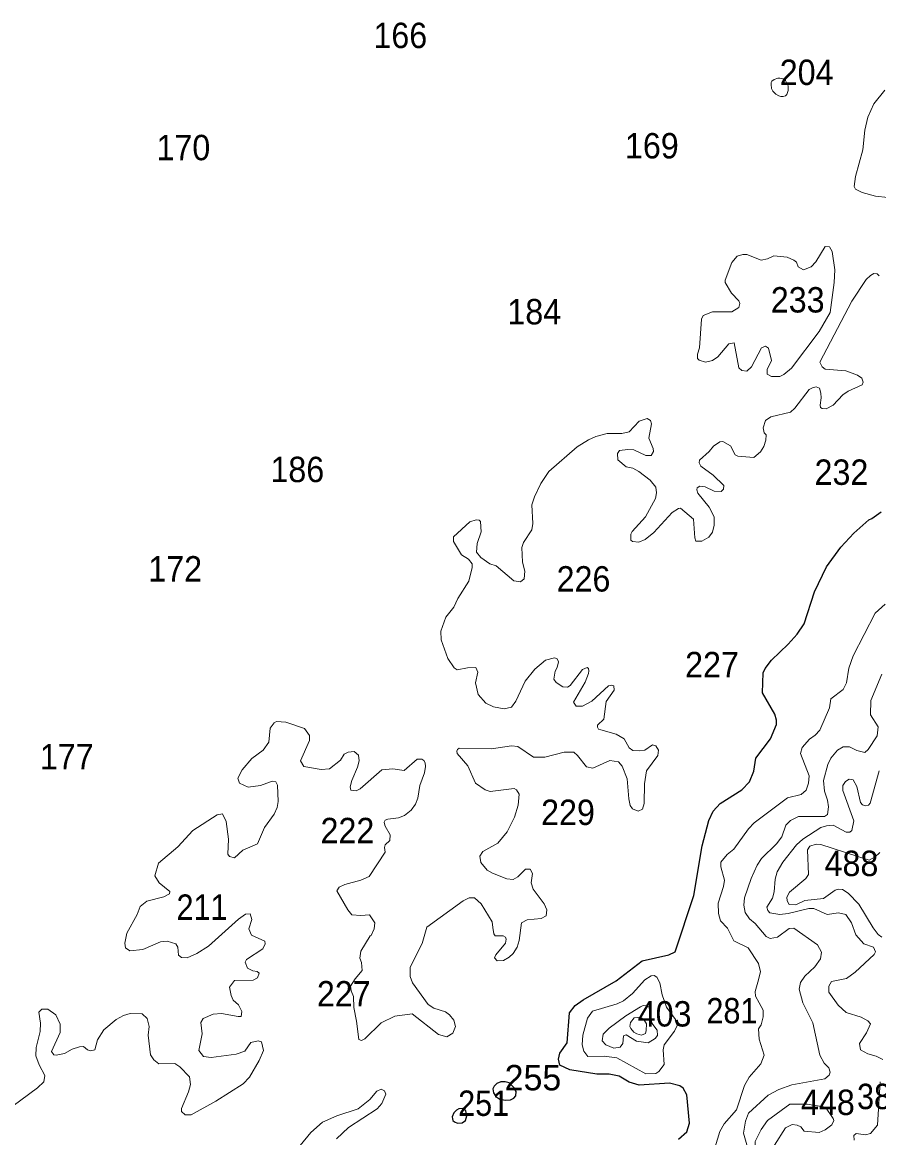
# Model space of a CAD drawing. Extents: x 499.9 to 555.3, y 9281.5 to 9336.8.
# Drawn here: x 530.94 to 536.34, y 9298.96 to 9305.99 of the extents above; entities that cross this region are included whole.
import ezdxf

# ---------------------------------------------------------------- set-up
doc = ezdxf.new("R2010")
doc.units = 0
doc.header["$LTSCALE"] = 0.064
doc.layers.add('1', color=7, linetype='Continuous', lineweight=25)
doc.layers.add('2', color=7, linetype='Continuous', lineweight=13)
doc.layers.add('21', color=7, linetype='Continuous')

msp = doc.modelspace()

# ---------------------------------------------------------------- linework, layer by layer
at = {"layer": '1'}
msp.add_lwpolyline([(535.0738, 9298.9508), (535.1263, 9298.9978), (535.1424, 9299.0519), (535.1247, 9299.2307), (535.1031, 9299.2737), (535.0811, 9299.2869), (535.016, 9299.3047), (534.8252, 9299.2909), (534.7623, 9299.3114), (534.6985, 9299.3493), (534.6349, 9299.362), (534.5573, 9299.3606), (534.387, 9299.3881), (534.3255, 9299.4173), (534.3158, 9299.4551), (534.3253, 9299.494), (534.3712, 9299.5597), (534.3857, 9299.7479), (534.4217, 9299.7933), (534.4724, 9299.8301), (534.6801, 9299.9499), (534.8444, 9300.0746), (535.0113, 9300.1132), (535.0516, 9300.1311), (535.1694, 9300.4866), (535.2214, 9300.7991), (535.2639, 9300.9592), (535.2919, 9301.0181), (535.3352, 9301.0666), (535.4726, 9301.1533), (535.5211, 9301.2038), (535.5483, 9301.2705), (535.5599, 9301.353), (535.6529, 9301.4751), (535.6913, 9301.5656), (535.6916, 9301.5919), (535.6804, 9301.6301), (535.6028, 9301.7639), (535.6064, 9301.8894), (535.619, 9301.9173), (535.6594, 9301.97), (535.7649, 9302.0712), (535.8205, 9302.1347), (535.8646, 9302.1993), (535.9308, 9302.4012), (536.0057, 9302.5587), (536.0954, 9302.6814), (536.1775, 9302.7699), (536.2727, 9302.8554), (536.2923, 9302.8632), (536.3497, 9302.9054)], dxfattribs=at)
for points in [[(533.9068, 9299.2428), (533.9217, 9299.2212), (533.9466, 9299.2046), (533.9832, 9299.198), (534.0131, 9299.1996), (534.0347, 9299.2096), (534.048, 9299.2246), (534.0497, 9299.2528), (534.0347, 9299.2777), (534.0048, 9299.3076), (533.9799, 9299.3126), (533.9533, 9299.3126), (533.9284, 9299.3027), (533.9101, 9299.286), (533.9018, 9299.2678)], [(533.6559, 9299.1182), (533.6459, 9299.0916), (533.6475, 9299.08), (533.6509, 9299.0684), (533.6608, 9299.0601), (533.6791, 9299.0534), (533.709, 9299.0551), (533.7306, 9299.07), (533.7389, 9299.0983), (533.7323, 9299.1298), (533.7123, 9299.1448), (533.6874, 9299.1431), (533.6725, 9299.1348)]]:
    msp.add_lwpolyline(points, close=True, dxfattribs=at)
at = {"layer": '2'}
for points in [[(535.6873, 9305.536), (535.7047, 9305.5257), (535.7182, 9305.5212), (535.7337, 9305.5212), (535.7485, 9305.5263), (535.7556, 9305.5347), (535.764, 9305.5592), (535.764, 9305.5882), (535.7485, 9305.623), (535.7337, 9305.6339), (535.7124, 9305.6378), (535.6989, 9305.6365), (535.677, 9305.6294), (535.6615, 9305.6191), (535.657, 9305.6101), (535.6564, 9305.5985), (535.659, 9305.5727), (535.668, 9305.5566)], [(535.9596, 9304.042), (536.0294, 9304.161), (536.055, 9304.3501), (536.0578, 9304.4289), (536.042, 9304.5443), (536.0255, 9304.5742), (535.997, 9304.577), (535.9391, 9304.4797), (535.9096, 9304.449), (535.8612, 9304.4302), (535.8273, 9304.449), (535.816, 9304.4782), (535.8004, 9304.4913), (535.7585, 9304.5091), (535.6746, 9304.5187), (535.6336, 9304.4996), (535.5938, 9304.4905), (535.5047, 9304.5264), (535.4794, 9304.5265), (535.4429, 9304.5149), (535.4082, 9304.4751), (535.3675, 9304.3652), (535.3671, 9304.3499), (535.4077, 9304.2822), (535.4543, 9304.2339), (535.459, 9304.2172), (535.4527, 9304.1933), (535.4091, 9304.1656), (535.2876, 9304.1643), (535.2294, 9304.1417), (535.2175, 9304.1181), (535.2061, 9303.9381), (535.1922, 9303.8973), (535.193, 9303.8701), (535.204, 9303.8598), (535.2436, 9303.8488), (535.2867, 9303.8581), (535.3213, 9303.8812), (535.3896, 9303.963), (535.4234, 9303.9692), (535.4526, 9303.8118), (535.4713, 9303.7947), (535.5044, 9303.7918), (535.5325, 9303.8186), (535.596, 9303.9386), (535.6206, 9303.9484), (535.6408, 9303.937), (535.6596, 9303.8584), (535.6315, 9303.8026), (535.6315, 9303.7731), (535.659, 9303.7581), (535.7126, 9303.7579), (535.7378, 9303.7708), (535.7844, 9303.8111)], [(534.5008, 9299.4717), (534.4758, 9299.5055), (534.4658, 9299.5457), (534.4695, 9299.6068), (534.4997, 9299.7142), (534.53, 9299.7578), (534.6873, 9299.8041), (534.7256, 9299.8229), (534.7833, 9299.8687), (534.8609, 9299.9552), (534.9006, 9299.9799), (534.9197, 9299.9825), (534.9367, 9299.972), (534.9559, 9299.9374), (534.9708, 9299.8603), (534.998, 9299.7833), (535.0545, 9299.7049), (535.0642, 9299.6669), (535.0475, 9299.6312), (534.9823, 9299.5456), (534.9772, 9299.5141), (534.9822, 9299.4218), (534.9488, 9299.3788), (534.9298, 9299.3664), (534.8673, 9299.3639), (534.6842, 9299.4639), (534.6048, 9299.4751)], [(534.8088, 9299.5691), (534.7428, 9299.6096), (534.7265, 9299.6031), (534.722, 9299.5543), (534.7051, 9299.5308), (534.6643, 9299.5254), (534.6155, 9299.5462), (534.5926, 9299.5703), (534.5986, 9299.6133), (534.6365, 9299.651), (534.7409, 9299.7297), (534.8329, 9299.7855), (534.8505, 9299.793), (534.8713, 9299.7916), (534.8851, 9299.7863), (534.8935, 9299.7538), (534.904, 9299.6826), (534.9376, 9299.6386), (534.9403, 9299.6048), (534.9254, 9299.5861), (534.8822, 9299.5586)], [(534.7708, 9299.6865), (534.7659, 9299.6616), (534.7725, 9299.65), (534.7908, 9299.6267), (534.8107, 9299.6151), (534.8396, 9299.6075), (534.8639, 9299.6167), (534.8689, 9299.6367), (534.8705, 9299.6782), (534.8539, 9299.7064), (534.8323, 9299.7197), (534.7941, 9299.7164)], [(535.8644, 9299.0025), (535.8436, 9299.0294), (535.8203, 9299.0409), (535.7888, 9299.0448), (535.7476, 9299.0225), (535.6781, 9298.9146), (535.6147, 9298.8555), (535.584, 9298.8541), (535.5631, 9298.8647), (535.5543, 9298.8836), (535.5559, 9298.9361), (535.594, 9299.0122), (535.6348, 9299.0691), (535.7746, 9299.1726), (535.885, 9299.1714), (535.9996, 9299.1534), (536.049, 9299.0818), (536.0525, 9299.0686), (536.0402, 9299.0411), (535.9979, 9299.0109), (535.9591, 9298.9928)]]:
    msp.add_lwpolyline(points, close=True, dxfattribs=at)
for points in [[(536.3918, 9304.8849), (536.3149, 9304.8931), (536.2313, 9304.916), (536.1889, 9304.9372), (536.1807, 9304.9543), (536.189, 9305.0172), (536.2342, 9305.185), (536.2471, 9305.3098), (536.2676, 9305.3919), (536.3045, 9305.4753), (536.3729, 9305.5611)], [(535.1754, 9302.7402), (535.1819, 9302.7201), (535.2194, 9302.7197), (535.265, 9302.746), (535.2869, 9302.7771), (535.2969, 9302.8214), (535.2969, 9302.8734), (535.2671, 9302.9343), (535.1952, 9303.022), (535.1881, 9303.0434), (535.1898, 9303.056), (535.2078, 9303.0662), (535.2406, 9303.0625), (535.2976, 9303.034), (535.3419, 9303.0338), (535.3561, 9303.047), (535.3584, 9303.0714), (535.2921, 9303.136), (535.2131, 9303.1929), (535.2036, 9303.2132), (535.2058, 9303.2307), (535.2661, 9303.2848), (535.2938, 9303.3186), (535.3345, 9303.3468), (535.3531, 9303.3486), (535.4018, 9303.3201), (535.4307, 9303.263), (535.4474, 9303.2552), (535.5473, 9303.2477), (535.5894, 9303.2837), (535.6104, 9303.3172), (535.6242, 9303.3568), (535.6247, 9303.391), (535.6123, 9303.4034), (535.6061, 9303.4333), (535.6223, 9303.48), (535.656, 9303.5031), (535.7789, 9303.533), (535.8059, 9303.557), (535.8972, 9303.675), (535.9169, 9303.6871), (535.94, 9303.6926), (535.962, 9303.6831), (535.9696, 9303.6518), (535.9718, 9303.6227), (535.9652, 9303.5769), (535.9674, 9303.5626), (535.9792, 9303.5552), (536.0029, 9303.553), (536.0487, 9303.5771), (536.1083, 9303.6412), (536.1422, 9303.6647), (536.2302, 9303.7053), (536.2372, 9303.7221), (536.2297, 9303.7461), (536.2025, 9303.7652), (536.1278, 9303.793), (535.9983, 9303.8032), (535.9779, 9303.8177), (535.9643, 9303.8481), (536.1648, 9304.2319), (536.2557, 9304.3692), (536.2828, 9304.3942), (536.3038, 9304.4069), (536.3263, 9304.4038), (536.3378, 9304.3929)], [(534.3737, 9301.8007), (534.3446, 9301.801), (534.3017, 9301.8283), (534.288, 9301.8504), (534.2945, 9301.9016), (534.3072, 9301.9237), (534.3163, 9301.9592), (534.3072, 9301.9779), (534.2916, 9301.9847), (534.2344, 9301.9708), (534.1663, 9301.9125), (534.1066, 9301.837), (534.0484, 9301.7114), (534.0197, 9301.6746), (533.9742, 9301.6637), (533.9062, 9301.6754), (533.8589, 9301.6998), (533.81, 9301.7527), (533.7931, 9301.8267), (533.8068, 9301.8936), (533.7943, 9301.9236), (533.7437, 9301.9213), (533.6785, 9301.9089), (533.6594, 9301.9217), (533.618, 9301.9801), (533.5768, 9302.0973), (533.5751, 9302.1521), (533.6066, 9302.2406), (533.6571, 9302.3043), (533.6825, 9302.3592), (533.7521, 9302.4689), (533.7722, 9302.5532), (533.7721, 9302.5779), (533.7483, 9302.6073), (533.704, 9302.6346), (533.6549, 9302.7181), (533.6551, 9302.7462), (533.7565, 9302.8411), (533.7977, 9302.8539), (533.8153, 9302.8528), (533.8251, 9302.8437), (533.8294, 9302.7784), (533.8041, 9302.706), (533.7994, 9302.6498), (533.826, 9302.616), (533.8831, 9302.5776), (533.9224, 9302.5638), (534.0345, 9302.4695), (534.0768, 9302.4632), (534.0997, 9302.482), (534.1031, 9302.5304), (534.0901, 9302.5883), (534.0844, 9302.6806), (534.0947, 9302.7108), (534.1476, 9302.7921), (534.1555, 9302.8316), (534.1482, 9302.9484), (534.1654, 9302.9989), (534.206, 9303.0833), (534.2555, 9303.1599), (534.4332, 9303.3138), (534.506, 9303.3593), (534.5522, 9303.3798), (534.623, 9303.3983), (534.7153, 9303.3985), (534.7616, 9303.4084), (534.826, 9303.4761), (534.8746, 9303.4935), (534.8956, 9303.4793), (534.902, 9303.4587), (534.8867, 9303.3692), (534.9134, 9303.3038), (534.9147, 9303.2854), (534.9005, 9303.2606), (534.8673, 9303.2602), (534.7916, 9303.2946), (534.7534, 9303.298), (534.7014, 9303.2919), (534.6892, 9303.2734), (534.6914, 9303.2321), (534.7432, 9303.1885), (534.7852, 9303.1799), (534.8227, 9303.1596), (534.8948, 9303.1048), (534.9309, 9303.06), (534.934, 9303.0243), (534.928, 9302.9879), (534.864, 9302.8732), (534.781, 9302.7817), (534.772, 9302.7633), (534.7722, 9302.7254), (534.7838, 9302.7172), (534.8219, 9302.7141), (534.8628, 9302.7295), (534.9177, 9302.7755)], [(534.9177, 9302.7755), (535.0338, 9302.9011), (535.0725, 9302.9254), (535.0863, 9302.927), (535.1665, 9302.8595), (535.1754, 9302.7402)], [(536.1111, 9301.7846), (536.1326, 9301.8267), (536.1469, 9301.9198), (536.1734, 9301.9971), (536.3133, 9302.2656), (536.3764, 9302.3227)], [(534.5081, 9301.9035), (534.5051, 9301.917), (534.4963, 9301.924), (534.4673, 9301.9112), (534.3901, 9301.8108), (534.3737, 9301.8007)], [(533.9683, 9300.2329), (533.9822, 9300.2251), (533.986, 9300.2109), (533.9813, 9300.1868), (533.922, 9300.1133), (533.9127, 9300.0937), (533.93, 9300.0755), (533.9688, 9300.0768), (534.0046, 9300.0975), (534.0309, 9300.1223), (534.0551, 9300.1621), (534.0682, 9300.2041), (534.0834, 9300.3142), (534.1187, 9300.3343), (534.2069, 9300.3418), (534.2381, 9300.3588), (534.2431, 9300.3974), (534.2253, 9300.4339), (534.1573, 9300.5264), (534.1447, 9300.5675), (534.1524, 9300.6267), (534.1369, 9300.6522), (534.1077, 9300.6523), (534.0592, 9300.6042), (534.0316, 9300.5885), (533.9905, 9300.5922), (533.9001, 9300.6275), (533.866, 9300.6469), (533.8266, 9300.6944), (533.8205, 9300.7356), (533.8397, 9300.7645), (533.9339, 9300.8165), (533.9927, 9300.8886), (534.0381, 9300.9799), (534.0619, 9301.0572), (534.0681, 9301.1264), (534.0525, 9301.152), (534.0364, 9301.1604), (533.8846, 9301.1433), (533.8534, 9301.1521), (533.7938, 9301.194), (533.744, 9301.3047), (533.6773, 9301.3817), (533.6746, 9301.3967), (533.6799, 9301.4073), (533.6902, 9301.4146), (533.894, 9301.4105), (534.0205, 9301.4295), (534.0601, 9301.4265), (534.1589, 9301.359), (534.2306, 9301.3597), (534.3531, 9301.3911), (534.4122, 9301.3899), (534.4369, 9301.3696), (534.4936, 9301.2972), (534.5322, 9301.2897), (534.6405, 9301.3368), (534.6941, 9301.3303), (534.7179, 9301.3015), (534.7489, 9301.2213), (534.759, 9301.0961), (534.7684, 9301.0548), (534.7836, 9301.033), (534.8189, 9301.0193), (534.8462, 9301.0305), (534.8559, 9301.066), (534.8592, 9301.1901), (534.8707, 9301.2735), (534.9428, 9301.3694), (534.9466, 9301.4024), (534.9307, 9301.4309), (534.9087, 9301.4371), (534.8601, 9301.4025), (534.8298, 9301.3979), (534.7847, 9301.4012), (534.7621, 9301.4175), (534.7298, 9301.4743), (534.6794, 9301.5043), (534.5837, 9301.5312), (534.5686, 9301.5363), (534.5621, 9301.5478), (534.5624, 9301.5606), (534.603, 9301.5976), (534.6173, 9301.7089), (534.6664, 9301.7814), (534.6662, 9301.8079), (534.6517, 9301.8128), (534.631, 9301.8077), (534.5255, 9301.7119), (534.4667, 9301.6807), (534.4272, 9301.6812), (534.4114, 9301.7063), (534.4837, 9301.8306), (534.5048, 9301.8863), (534.5081, 9301.9035)], [(535.5961, 9300.7212), (535.6911, 9300.8119), (535.7237, 9300.8574), (535.7493, 9300.9297), (535.7784, 9300.9607), (535.8286, 9300.9853), (535.9933, 9300.984), (536.0127, 9300.9969), (536.0195, 9301.0462), (536.0128, 9301.0888), (535.9944, 9301.1456), (535.9879, 9301.2115), (536.0135, 9301.3125), (536.0335, 9301.3525), (536.0745, 9301.4029), (536.1119, 9301.423), (536.1514, 9301.4247), (536.1964, 9301.4004), (536.2486, 9301.3886), (536.2682, 9301.408), (536.3249, 9301.4933), (536.3313, 9301.5499), (536.2827, 9301.6263), (536.2856, 9301.7168), (536.3551, 9301.8809)], [(535.8987, 9301.4725), (535.9336, 9301.4965), (535.9637, 9301.5283), (536.0252, 9301.6698), (536.0326, 9301.7255), (536.1111, 9301.7846)], [(532.3221, 9301.278), (532.3821, 9301.3505), (532.4538, 9301.4021), (532.4896, 9301.4536), (532.499, 9301.5419), (532.5232, 9301.5758)], [(532.5232, 9301.5758), (532.5394, 9301.5839), (532.597, 9301.5793), (532.7153, 9301.5392), (532.747, 9301.4963), (532.7469, 9301.4639), (532.6904, 9301.3347), (532.7115, 9301.2991), (532.8198, 9301.2817), (532.8717, 9301.2846), (532.9428, 9301.3404), (532.9645, 9301.3773), (532.991, 9301.3907), (533.0273, 9301.3941), (533.0546, 9301.3718), (533.0588, 9301.3356), (533.0495, 9301.296), (533.0126, 9301.2114), (533.0037, 9301.1718), (533.0076, 9301.1505), (533.0404, 9301.1463), (533.065, 9301.1587), (533.203, 9301.2794), (533.2717, 9301.2863), (533.3439, 9301.2755), (533.4245, 9301.3462), (533.4554, 9301.3468), (533.4668, 9301.3373), (533.476, 9301.3238), (533.4788, 9301.299), (533.4713, 9301.261), (533.4417, 9301.1799), (533.4288, 9301.1002), (533.4138, 9301.0633), (533.387, 9301.0254), (533.345, 9300.9917), (533.3068, 9300.976), (533.2407, 9300.9672), (533.2238, 9300.9609), (533.2183, 9300.9487), (533.2186, 9300.9386), (533.2236, 9300.9236), (533.2561, 9300.869), (533.2535, 9300.834), (533.2231, 9300.8066), (533.2187, 9300.7906), (533.2241, 9300.7592), (533.1233, 9300.6065), (533.0712, 9300.5827), (532.9685, 9300.5566), (532.9327, 9300.5386), (532.918, 9300.5155), (532.9889, 9300.3959), (533.0135, 9300.3662), (533.07, 9300.3602), (533.1244, 9300.3645), (533.1578, 9300.315), (533.1532, 9300.2781), (533.1358, 9300.2355), (533.1292, 9300.2335), (533.0705, 9300.1372), (533.0641, 9300.0923), (533.0749, 9300.0654), (533.0782, 9300.0139), (533.0338, 9299.9621), (533.0054, 9299.9167), (533.0084, 9299.8867), (533.0239, 9299.8514), (533.026, 9299.7816), (533.0438, 9299.6944), (533.0578, 9299.5791), (533.0754, 9299.5732), (533.0964, 9299.5834), (533.198, 9299.685), (533.2853, 9299.7265), (533.3933, 9299.7407), (533.5607, 9299.6115), (533.6124, 9299.5963), (533.6492, 9299.6196), (533.667, 9299.6623), (533.657, 9299.7017), (533.6295, 9299.7355), (533.6041, 9299.7547), (533.5303, 9299.7779), (533.4939, 9299.8), (533.3967, 9299.9368), (533.3811, 9299.9774), (533.3812, 9300.0345), (533.4568, 9300.1843), (533.4862, 9300.2867), (533.7159, 9300.4535), (533.7532, 9300.4728), (533.7875, 9300.4724), (533.8289, 9300.4338), (533.8989, 9300.3216)], [(535.2746, 9298.8067), (535.3337, 9299.0008), (535.3612, 9299.0492), (535.438, 9299.1371), (535.488, 9299.2905), (535.519, 9299.3415), (535.5913, 9299.426), (535.6136, 9299.4809), (535.5818, 9299.581), (535.5776, 9299.6459), (535.5931, 9299.6718), (535.6065, 9299.7234), (535.6064, 9299.7646), (535.5808, 9299.8114), (535.5577, 9299.8531), (535.5571, 9299.8826), (535.5725, 9299.9404), (535.5891, 9300.0066), (535.577, 9300.0594), (535.5114, 9300.1563), (535.4214, 9300.2012), (535.3812, 9300.2805), (535.3379, 9300.3285), (535.3256, 9300.3736), (535.3225, 9300.4381), (535.3572, 9300.544), (535.362, 9300.5842), (535.3388, 9300.6671), (535.3389, 9300.6964), (535.3792, 9300.7446), (535.4227, 9300.7787), (535.5135, 9300.9075), (535.5498, 9300.945), (535.7603, 9301.1023), (535.8459, 9301.1235), (535.8779, 9301.1515), (535.8931, 9301.1953), (535.8968, 9301.2418), (535.8415, 9301.3811), (535.8521, 9301.419), (535.8987, 9301.4725)], [(531.9835, 9299.2499), (531.9388, 9299.1459), (531.9392, 9299.1252), (531.963, 9299.1046), (532.0014, 9299.1054), (532.1568, 9299.1915), (532.3286, 9299.3006), (532.3674, 9299.3417), (532.429, 9299.4466), (532.4568, 9299.5113), (532.4441, 9299.5658), (532.4219, 9299.5704), (532.3769, 9299.5601), (532.338, 9299.5056), (532.2833, 9299.4867), (532.1274, 9299.4658), (532.0776, 9299.4718), (532.0489, 9299.511), (532.0706, 9299.6152), (532.0615, 9299.6877), (532.0754, 9299.7116), (532.1386, 9299.7389), (532.1926, 9299.744), (532.2966, 9299.7237), (532.3155, 9299.7256), (532.3198, 9299.7569), (532.2983, 9299.7981), (532.2659, 9299.8284), (532.2522, 9299.8579), (532.2418, 9299.9086), (532.2738, 9299.9519), (532.3907, 9299.9529), (532.4191, 9299.9687), (532.4286, 9299.9986), (532.4173, 9300.0075), (532.3902, 9300.0119), (532.3564, 9300.0289), (532.3403, 9300.0664), (532.3494, 9300.0847), (532.452, 9300.151), (532.4671, 9300.1832), (532.4654, 9300.2001), (532.3814, 9300.2376), (532.3647, 9300.278), (532.384, 9300.3354), (532.3714, 9300.3707), (532.344, 9300.3705), (532.2987, 9300.3386), (532.1101, 9300.1686), (532.0364, 9300.122), (531.9745, 9300.0946), (531.939, 9300.0962), (531.9204, 9300.1114), (531.9165, 9300.1619), (531.9041, 9300.1825), (531.8482, 9300.1988), (531.8077, 9300.1959), (531.6968, 9300.1468), (531.6142, 9300.1375), (531.5865, 9300.1573), (531.5824, 9300.1867), (531.5951, 9300.2503), (531.6594, 9300.368), (531.6789, 9300.4169), (531.7218, 9300.452), (531.8274, 9300.4779), (531.8649, 9300.4983), (531.8656, 9300.5129), (531.7996, 9300.566), (531.7707, 9300.6109), (531.7949, 9300.6905), (531.9159, 9300.794), (532.012, 9300.8963), (532.1642, 9300.9963), (532.1989, 9301.0013), (532.2206, 9300.9536), (532.2362, 9300.8415), (532.2313, 9300.7472), (532.2419, 9300.732), (532.2735, 9300.7237), (532.3256, 9300.7721), (532.4186, 9300.8135), (532.4632, 9300.9155), (532.5228, 9301), (532.5431, 9301.0406), (532.5482, 9301.0802), (532.5443, 9301.1829), (532.5336, 9301.2027), (532.5112, 9301.2081), (532.4776, 9301.1957), (532.4368, 9301.1795), (532.359, 9301.1688), (532.3059, 9301.1948), (532.2954, 9301.2262), (532.3221, 9301.278)], [(536.361, 9299.4532), (536.3187, 9299.475), (536.2672, 9299.4898), (536.2203, 9299.5152), (536.2142, 9299.5536), (536.2586, 9299.6207), (536.2833, 9299.6777), (536.2675, 9299.6964), (536.224, 9299.7198), (536.1299, 9299.75), (536.0801, 9299.7967), (536.0217, 9299.8788), (536.0197, 9299.9168), (536.0373, 9299.9443), (536.1325, 9299.9639), (536.1863, 9300.0031), (536.3071, 9300.1144), (536.315, 9300.1315), (536.3031, 9300.1615), (536.2404, 9300.1815), (536.1916, 9300.2392), (536.1626, 9300.3155), (536.1269, 9300.3665), (536.0808, 9300.3776), (536.0101, 9300.3683), (535.9267, 9300.405), (535.8947, 9300.406), (535.7641, 9300.374), (535.7126, 9300.3683), (535.6494, 9300.377), (535.6365, 9300.3929), (535.6299, 9300.4143), (535.6662, 9300.4708), (535.6756, 9300.5098), (535.6816, 9300.5891), (535.6957, 9300.6355), (535.73, 9300.6974), (535.8173, 9300.8054), (535.8578, 9300.8427), (535.9696, 9300.9151), (536.0052, 9300.9261), (536.0489, 9300.9293), (536.131, 9300.8871), (536.154, 9300.887), (536.1654, 9300.8977), (536.1785, 9300.9569), (536.1088, 9301.1495), (536.1088, 9301.1805), (536.1249, 9301.2049), (536.1483, 9301.221), (536.1739, 9301.2157), (536.1977, 9301.1749), (536.22, 9301.0737), (536.232, 9301.0591), (536.252, 9301.0527), (536.2703, 9301.0571), (536.2804, 9301.0685), (536.3373, 9301.2719)], [(536.3419, 9300.7575), (536.3126, 9300.731), (536.2757, 9300.709), (535.9705, 9300.8084), (535.94, 9300.8103), (535.9019, 9300.7975), (535.8859, 9300.7739), (535.8917, 9300.619), (535.8757, 9300.5951), (535.772, 9300.5085), (535.7561, 9300.4762), (535.7585, 9300.4531), (535.7711, 9300.4294), (535.8117, 9300.4287), (535.8693, 9300.4553), (535.9871, 9300.4682), (536.0613, 9300.5206), (536.0824, 9300.528), (536.1079, 9300.525), (536.1425, 9300.5026), (536.209, 9300.4315), (536.3001, 9300.283), (536.3321, 9300.242), (536.3555, 9300.2249)], [(535.4922, 9300.3808), (535.4849, 9300.4262), (535.4896, 9300.4715), (535.5307, 9300.5949), (535.568, 9300.6791), (535.5961, 9300.7212)], [(535.507, 9298.9022), (535.4833, 9298.9894), (535.4952, 9299.066), (535.5153, 9299.1161), (535.6376, 9299.2283), (535.706, 9299.2642), (535.7872, 9299.2937), (535.996, 9299.331), (536.0233, 9299.3545), (536.0288, 9299.3734), (536.0197, 9299.4012), (535.9915, 9299.4316), (535.9649, 9299.4801), (535.9192, 9299.6852), (535.8576, 9299.8118), (535.8336, 9299.8978), (535.8431, 9299.9399), (535.8694, 9299.9783), (535.9335, 9300.037), (535.9676, 9300.0875), (535.9746, 9300.1309), (535.9494, 9300.1754), (535.7997, 9300.2817), (535.7697, 9300.2795), (535.6967, 9300.224), (535.6517, 9300.2169), (535.6255, 9300.2294), (535.5569, 9300.3116), (535.52, 9300.3395), (535.4922, 9300.3808)], [(533.8989, 9300.3216), (533.9032, 9300.2862), (533.9082, 9300.2447), (533.9175, 9300.2329), (533.9488, 9300.2337), (533.9683, 9300.2329)], [(530.8216, 9299.1196), (531.0319, 9299.2756), (531.0718, 9299.3134), (531.0788, 9299.3532), (531.0412, 9299.4211), (531.0221, 9299.4771), (531.0238, 9299.5292), (531.049, 9299.6311), (531.0505, 9299.682), (531.0396, 9299.7521), (531.0595, 9299.7709), (531.0959, 9299.7705), (531.1477, 9299.7341), (531.1744, 9299.6765), (531.1744, 9299.624), (531.1194, 9299.5034), (531.1355, 9299.4826), (531.1494, 9299.4802), (531.2027, 9299.4925), (531.2497, 9299.5181), (531.2965, 9299.534), (531.3211, 9299.5352), (531.3462, 9299.5139), (531.366, 9299.5074), (531.3935, 9299.5149), (531.4108, 9299.5777), (531.4489, 9299.6398), (531.5282, 9299.7059), (531.5735, 9299.7315), (531.615, 9299.7425), (531.6921, 9299.7411), (531.7225, 9299.713), (531.7363, 9299.6606), (531.7304, 9299.6069), (531.7443, 9299.484), (531.7644, 9299.4512), (531.7956, 9299.4257)], [(531.7956, 9299.4257), (531.8965, 9299.4285), (531.9298, 9299.4077), (531.9898, 9299.3454), (531.9959, 9299.2966), (531.9835, 9299.2499)], [(532.9161, 9298.9531), (532.9923, 9299.0242), (533.1723, 9299.1432), (533.2028, 9299.1762), (533.2276, 9299.2349), (533.2197, 9299.2567), (533.1991, 9299.2674), (533.1719, 9299.255), (533.1271, 9299.2009), (533.0535, 9299.143)], [(536.1811, 9298.9451), (536.1792, 9298.9749), (536.1924, 9298.9871), (536.2518, 9298.9799), (536.2833, 9298.9871), (536.3274, 9299.0399), (536.3442, 9299.3121)], [(533.0535, 9299.143), (532.9193, 9299.0995), (532.8294, 9299.0592), (532.7542, 9298.9935), (532.6885, 9298.9117), (532.5908, 9298.7317)]]:
    msp.add_lwpolyline(points, dxfattribs=at)

# ---------------------------------------------------------------- texts
at = {"layer": '21'}
for s, width, p in [('166', 0.95, (533.1494, 9305.8271)), ('204', 0.95, (535.7112, 9305.5944)), ('169', 0.95, (534.7354, 9305.1318)), ('170', 0.95, (531.7818, 9305.1203)), ('233', 0.95, (535.6548, 9304.1607)), ('184', 0.95, (533.9941, 9304.086)), ('186', 0.95, (532.5001, 9303.0919)), ('232', 0.95, (535.9306, 9303.0747)), ('172', 0.95, (531.7301, 9302.4656)), ('226', 0.95, (534.3044, 9302.4024)), ('227', 0.95, (535.1146, 9301.8622)), ('177', 0.95, (531.0463, 9301.2818)), ('229', 0.95, (534.2067, 9300.9313)), ('222', 0.95, (532.8161, 9300.8164)), ('488', 0.95, (535.9938, 9300.6095)), ('211', 0.9, (531.9082, 9300.3337)), ('227', 0.95, (532.7931, 9299.7878)), ('403', 0.95, (534.8158, 9299.6614)), ('281', 0.9, (535.2491, 9299.6813)), ('251', 0.9, (533.6838, 9299.0982)), ('448', 0.95, (535.8453, 9299.1039)), ('381', 0.9, (536.1986, 9299.1408))]:
    msp.add_text(s, height=0.16, dxfattribs=dict(at, width=width)).set_placement(p)
msp.add_text('255', height=0.16, dxfattribs=at).set_placement((533.9768, 9299.2592))

doc.saveas('drawing.dxf')
